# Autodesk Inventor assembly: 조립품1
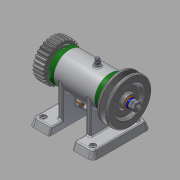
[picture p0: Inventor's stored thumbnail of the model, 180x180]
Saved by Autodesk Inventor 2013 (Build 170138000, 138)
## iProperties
Created: 2016-07
Part Number: 조립품1
Document SubType Name: Assembly
Designer: Administrator
Author: Administrator
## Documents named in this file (16)
- C:\Users\Administrator\Desktop\460708V1024\조립품1.iam
- C:\Users\Administrator\Desktop\460708V1024\본체.ipt
- C:\Users\Administrator\Desktop\460708V1024\V벨트풀리.ipt
- C:\Users\Administrator\Desktop\460708V1024\너트 M 8.ipt
- C:\Users\Administrator\Desktop\460708V1024\니플 M 6 x 0.75.ipt
- C:\Users\Administrator\Desktop\460708V1024\베어링 15 x 32 x 9.ipt
- C:\Users\Administrator\Desktop\460708V1024\볼트 M 6 x 8.ipt
- C:\Users\Administrator\Desktop\460708V1024\볼트 M4 x 12.ipt
- C:\Users\Administrator\Desktop\460708V1024\스퍼기어.ipt
- C:\Users\Administrator\Desktop\460708V1024\스프링와셔 8.ipt
- C:\Users\Administrator\Desktop\460708V1024\오일 실 15 25 7.ipt
- C:\Users\Administrator\Desktop\460708V1024\와셔 6x11.5.ipt
- C:\Users\Administrator\Desktop\460708V1024\와셔 8x17.ipt
- C:\Users\Administrator\Desktop\460708V1024\축.ipt
- C:\Users\Administrator\Desktop\460708V1024\커버.ipt
- C:\Users\Administrator\Desktop\460708V1024\키 3 x 3 x 12.ipt
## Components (11 placed, 3 different names)
1. V벨트풀리:1
2. KS B 2023 6002 - 15 x 32 x 9:1
3. KS B 2023 6002 - 15 x 32 x 9:2
4. ISO 4762 M4 x 12:1
5. ISO 4762 M4 x 12:2
6. ISO 4762 M4 x 12:3
7. ISO 4762 M4 x 12:4
8. ISO 4762 M4 x 12:5
9. ISO 4762 M4 x 12:6
10. ISO 4762 M4 x 12:7
11. ISO 4762 M4 x 12:8
